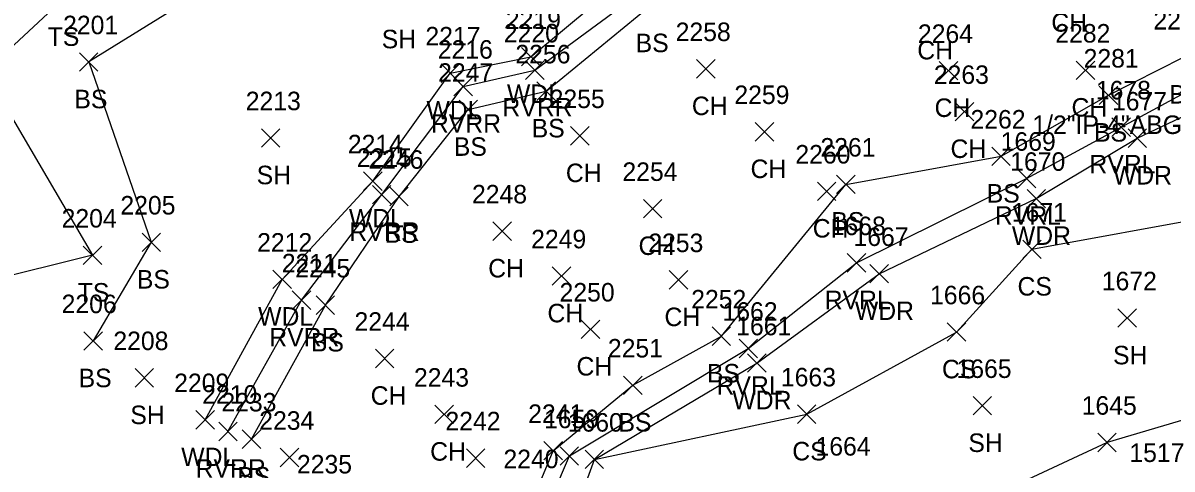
# Model space of a CAD drawing. Extents: x 1501299 to 1502485, y 381423 to 383765.
# Drawn here: x 1501473.5 to 1501597.6, y 383226.1 to 383274.3 of the extents above; entities that cross this region are included whole.
import ezdxf

# ---------------------------------------------------------------- set-up
doc = ezdxf.new("R2010")
doc.units = 0
for name, color, linetype in [('L_A', 7, 'Continuous'), ('L_I', 7, 'Continuous'), ('L_TIC', 7, 'Continuous'), ('LAWA', 7, 'Continuous'), ('LAWE', 7, 'Continuous'), ('LELB', 7, 'Continuous'), ('M_C', 7, 'Continuous')]:
    doc.layers.add(name, color=color, linetype=linetype)

msp = doc.modelspace()

# ---------------------------------------------------------------- linework, layer by layer
at = {"layer": 'L_TIC'}
for points in [[(1501479.6, 383269.06), (1501481.6, 383271.06)], [(1501481.6, 383269.06), (1501479.6, 383271.06)], [(1501527.36, 383269.63), (1501529.36, 383271.63)], [(1501529.36, 383269.63), (1501527.36, 383271.63)], [(1501518.66, 383267.85), (1501520.66, 383269.85)], [(1501520.66, 383267.85), (1501518.66, 383269.85)], [(1501527.78, 383268.18), (1501529.78, 383270.18)], [(1501529.78, 383268.18), (1501527.78, 383270.18)], [(1501546.26, 383268.32), (1501548.26, 383270.32)], [(1501548.26, 383268.32), (1501546.26, 383270.32)], [(1501572.48, 383268.12), (1501574.48, 383270.12)], [(1501574.48, 383268.12), (1501572.48, 383270.12)], [(1501587.27, 383268.16), (1501589.27, 383270.16)], [(1501589.27, 383268.16), (1501587.27, 383270.16)], [(1501520.04, 383266.42), (1501522.04, 383268.42)], [(1501522.04, 383266.42), (1501520.04, 383268.42)], [(1501529.01, 383265.91), (1501531.01, 383267.91)], [(1501531.01, 383265.91), (1501529.01, 383267.91)], [(1501589.76, 383265.46), (1501591.76, 383267.46)], [(1501591.76, 383265.46), (1501589.76, 383267.46)], [(1501520.6, 383263.92), (1501522.6, 383265.92)], [(1501522.6, 383263.92), (1501520.6, 383265.92)], [(1501574.2, 383263.69), (1501576.2, 383265.69)], [(1501576.2, 383263.69), (1501574.2, 383265.69)], [(1501552.6, 383261.52), (1501554.6, 383263.52)], [(1501554.6, 383261.52), (1501552.6, 383263.52)], [(1501591.13, 383262.02), (1501593.13, 383264.02)], [(1501593.13, 383262.02), (1501591.13, 383264.02)], [(1501499.25, 383260.85), (1501501.25, 383262.85)], [(1501501.25, 383260.85), (1501499.25, 383262.85)], [(1501532.65, 383261.08), (1501534.65, 383263.08)], [(1501534.65, 383261.08), (1501532.65, 383263.08)], [(1501592.87, 383260.82), (1501594.87, 383262.82)], [(1501594.87, 383260.82), (1501592.87, 383262.82)], [(1501578.15, 383258.87), (1501580.15, 383260.87)], [(1501580.15, 383258.87), (1501578.15, 383260.87)], [(1501580.91, 383256.47), (1501582.91, 383258.47)], [(1501582.91, 383256.47), (1501580.91, 383258.47)], [(1501510.28, 383256.19), (1501512.28, 383258.19)], [(1501512.28, 383256.19), (1501510.28, 383258.19)], [(1501559.32, 383255.09), (1501561.32, 383257.09)], [(1501561.32, 383255.09), (1501559.32, 383257.09)], [(1501561.38, 383255.84), (1501563.38, 383257.84)], [(1501563.38, 383255.84), (1501561.38, 383257.84)], [(1501511.25, 383254.73), (1501513.25, 383256.73)], [(1501513.25, 383254.73), (1501511.25, 383256.73)], [(1501513.12, 383254.52), (1501515.12, 383256.52)], [(1501515.12, 383254.52), (1501513.12, 383256.52)], [(1501581.96, 383254.3), (1501583.96, 383256.3)], [(1501583.96, 383254.3), (1501581.96, 383256.3)], [(1501540.51, 383253.21), (1501542.51, 383255.21)], [(1501542.51, 383253.21), (1501540.51, 383255.21)], [(1501524.26, 383250.78), (1501526.26, 383252.78)], [(1501526.26, 383250.78), (1501524.26, 383252.78)], [(1501486.36, 383249.58), (1501488.36, 383251.58)], [(1501488.36, 383249.58), (1501486.36, 383251.58)], [(1501480.01, 383248.17), (1501482.01, 383250.17)], [(1501482.01, 383248.17), (1501480.01, 383250.17)], [(1501581.49, 383248.82), (1501583.49, 383250.82)], [(1501583.49, 383248.82), (1501581.49, 383250.82)], [(1501562.53, 383247.35), (1501564.53, 383249.35)], [(1501564.53, 383247.35), (1501562.53, 383249.35)], [(1501500.49, 383245.57), (1501502.49, 383247.57)], [(1501502.49, 383245.57), (1501500.49, 383247.57)], [(1501530.66, 383245.93), (1501532.66, 383247.93)], [(1501532.66, 383245.93), (1501530.66, 383247.93)], [(1501543.3, 383245.52), (1501545.3, 383247.52)], [(1501545.3, 383245.52), (1501543.3, 383247.52)], [(1501564.99, 383246.18), (1501566.99, 383248.18)], [(1501566.99, 383246.18), (1501564.99, 383248.18)], [(1501502.59, 383243.33), (1501504.59, 383245.33)], [(1501504.59, 383243.33), (1501502.59, 383245.33)], [(1501505.16, 383242.78), (1501507.16, 383244.78)], [(1501507.16, 383242.78), (1501505.16, 383244.78)], [(1501591.77, 383241.39), (1501593.77, 383243.39)], [(1501593.77, 383241.39), (1501591.77, 383243.39)], [(1501533.8, 383240.18), (1501535.8, 383242.18)], [(1501535.8, 383240.18), (1501533.8, 383242.18)], [(1501547.94, 383239.43), (1501549.94, 383241.43)], [(1501549.94, 383239.43), (1501547.94, 383241.43)], [(1501573.33, 383239.88), (1501575.33, 383241.88)], [(1501575.33, 383239.88), (1501573.33, 383241.88)], [(1501480.07, 383238.92), (1501482.07, 383240.92)], [(1501482.07, 383238.92), (1501480.07, 383240.92)], [(1501550.85, 383238.1), (1501552.85, 383240.1)], [(1501552.85, 383238.1), (1501550.85, 383240.1)], [(1501511.57, 383237.02), (1501513.57, 383239.02)], [(1501513.57, 383237.02), (1501511.57, 383239.02)], [(1501551.76, 383236.53), (1501553.76, 383238.53)], [(1501553.76, 383236.53), (1501551.76, 383238.53)], [(1501485.6, 383234.93), (1501487.6, 383236.93)], [(1501487.6, 383234.93), (1501485.6, 383236.93)], [(1501538.38, 383234.13), (1501540.38, 383236.13)], [(1501540.38, 383234.13), (1501538.38, 383236.13)], [(1501576.13, 383231.92), (1501578.13, 383233.92)], [(1501578.13, 383231.92), (1501576.13, 383233.92)], [(1501492.17, 383230.39), (1501494.17, 383232.39)], [(1501494.17, 383230.39), (1501492.17, 383232.39)], [(1501517.99, 383230.98), (1501519.99, 383232.98)], [(1501519.99, 383230.98), (1501517.99, 383232.98)], [(1501557.16, 383231.01), (1501559.16, 383233.01)], [(1501559.16, 383231.01), (1501557.16, 383233.01)], [(1501494.64, 383229.14), (1501496.64, 383231.14)], [(1501496.64, 383229.14), (1501494.64, 383231.14)], [(1501497.19, 383228.3), (1501499.19, 383230.3)], [(1501499.19, 383228.3), (1501497.19, 383230.3)], [(1501589.6, 383227.95), (1501591.6, 383229.95)], [(1501591.6, 383227.95), (1501589.6, 383229.95)], [(1501529.77, 383227.06), (1501531.77, 383229.06)], [(1501531.77, 383227.06), (1501529.77, 383229.06)], [(1501501.28, 383226.32), (1501503.28, 383228.32)], [(1501503.28, 383226.32), (1501501.28, 383228.32)], [(1501521.39, 383226.26), (1501523.39, 383228.26)], [(1501523.39, 383226.26), (1501521.39, 383228.26)], [(1501531.52, 383226.49), (1501533.52, 383228.49)], [(1501533.52, 383226.49), (1501531.52, 383228.49)], [(1501534.22, 383226.12), (1501536.22, 383228.12)], [(1501536.22, 383226.12), (1501534.22, 383228.12)], [(1501534.22, 383226.12), (1501536.22, 383228.12)], [(1501536.22, 383226.12), (1501534.22, 383228.12)]]:
    msp.add_lwpolyline(points, dxfattribs=at)
at = {"layer": 'LAWA'}
for points in [[(1501493.17, 383231.39), (1501501.49, 383246.57), (1501511.28, 383257.19), (1501519.66, 383268.85), (1501528.36, 383270.63), (1501542.05, 383282.05), (1501551.39, 383287.43), (1501560.18, 383293.04)], [(1501523.12, 383213.31), (1501532.43, 383219.38), (1501535.22, 383227.12), (1501552.76, 383237.53), (1501565.99, 383247.18), (1501582.96, 383255.3), (1501593.87, 383261.82), (1501604.57, 383266.91)]]:
    msp.add_lwpolyline(points, dxfattribs=at)
at = {"layer": 'LAWE'}
for points in [[(1501495.64, 383230.14), (1501503.59, 383244.33), (1501512.25, 383255.73), (1501521.04, 383267.42), (1501528.78, 383269.18), (1501542.64, 383279.39), (1501552.31, 383285.91), (1501562.62, 383292.35), (1501575.76, 383300.88), (1501583.22, 383301.34), (1501587.9, 383304.38)], [(1501505.16, 383203.17), (1501520.7, 383214.78), (1501528.92, 383219.09), (1501532.52, 383227.49), (1501551.85, 383239.1), (1501563.53, 383248.35), (1501581.91, 383257.47), (1501592.13, 383263.02), (1501602.49, 383268.62), (1501606.54, 383268.13), (1501609.9, 383267.24)]]:
    msp.add_lwpolyline(points, dxfattribs=at)
at = {"layer": 'LELB'}
for points in [[(1501498.19, 383229.3), (1501506.16, 383243.78), (1501514.12, 383255.52), (1501521.6, 383264.92), (1501530.01, 383266.91), (1501541.24, 383276.12), (1501565.52, 383288.26), (1501578.59, 383296.73), (1501585.35, 383299.26), (1501590.26, 383300.86), (1501600.8, 383297.99), (1501605.17, 383301.4), (1501610.7, 383306.05), (1501616.47, 383310.93), (1501623.41, 383316.64), (1501624.75, 383320.37)], [(1501529.79, 383319.02), (1501508.47, 383318.79), (1501498.45, 383314.16), (1501488.16, 383291.02), (1501493.84, 383282.99), (1501477.76, 383276.8), (1501469.37, 383268.99), (1501481.01, 383249.17), (1501469.56, 383246.34)], [(1501529.79, 383319.02), (1501511.35, 383311.94), (1501505.3, 383294.67), (1501497.78, 383280.73), (1501480.6, 383270.06), (1501487.36, 383250.58), (1501481.07, 383239.92)], [(1501528.75, 383223.17), (1501530.77, 383228.06), (1501539.38, 383235.13), (1501548.94, 383240.43), (1501562.38, 383256.84), (1501579.15, 383259.87), (1501590.76, 383266.46), (1501598.87, 383270.57)], [(1501535.22, 383227.12), (1501558.16, 383232.01), (1501574.33, 383240.88), (1501582.49, 383249.82), (1501602.25, 383253.43), (1501611.93, 383256.47)], [(1501605.35, 383233.31), (1501590.6, 383228.95), (1501573.55, 383221), (1501565.09, 383213.34), (1501549.82, 383204.98), (1501532.49, 383198.66), (1501516.24, 383190.97)]]:
    msp.add_lwpolyline(points, dxfattribs=at)

# ---------------------------------------------------------------- texts
at = {"layer": 'L_A'}
for s, p in [('CH', (1501584.58, 383273.34)), ('TS', (1501476.17, 383271.8)), ('SH', (1501512.25, 383271.54)), ('BS', (1501539.68, 383271.12)), ('CH', (1501570.1, 383270.34)), ('BS', (1501479.05, 383265.06)), ('WDL', (1501525.78, 383265.63)), ('BS', (1501597.31, 383265.57)), ('WDL', (1501517.08, 383263.85)), ('RVRR', (1501525.29, 383264.18)), ('CH', (1501545.75, 383264.32)), ('CH', (1501571.97, 383264.12)), ('CH', (1501586.76, 383264.16)), ('RVRR', (1501517.56, 383262.42)), ('BS', (1501528.45, 383261.91)), ('BS', (1501589.2, 383261.46)), ('BS', (1501520.04, 383259.92)), ('CH', (1501573.69, 383259.69)), ('RVRL', (1501588.7, 383258.02)), ('SH', (1501498.74, 383256.85)), ('CH', (1501532.14, 383257.08)), ('CH', (1501552.09, 383257.52)), ('WDR', (1501591.23, 383256.82)), ('BS', (1501577.6, 383254.87)), ('WDL', (1501508.7, 383252.19)), ('BS', (1501560.82, 383251.84)), ('RVRL', (1501578.48, 383252.47)), ('RVRR', (1501508.76, 383250.73)), ('BS', (1501512.56, 383250.52)), ('CH', (1501558.81, 383251.09)), ('WDR', (1501580.32, 383250.3)), ('CH', (1501539.99, 383249.21)), ('CH', (1501523.75, 383246.78)), ('BS', (1501485.8, 383245.58)), ('TS', (1501479.41, 383244.17)), ('CS', (1501580.93, 383244.82)), ('RVRL', (1501560.1, 383243.35)), ('WDL', (1501498.9, 383241.57)), ('CH', (1501530.15, 383241.93)), ('CH', (1501542.79, 383241.52)), ('WDR', (1501563.36, 383242.18)), ('RVRR', (1501500.1, 383239.33)), ('BS', (1501504.6, 383238.78)), ('SH', (1501591.25, 383237.39)), ('CH', (1501533.29, 383236.18)), ('BS', (1501547.38, 383235.43)), ('CS', (1501572.77, 383235.88)), ('BS', (1501479.51, 383234.92)), ('RVRL', (1501548.42, 383234.1)), ('CH', (1501511.06, 383233.02)), ('WDR', (1501550.13, 383232.53)), ('SH', (1501485.09, 383230.93)), ('BS', (1501537.82, 383230.13)), ('SH', (1501575.62, 383227.92)), ('CH', (1501517.48, 383226.98)), ('CS', (1501556.6, 383227.01)), ('WDL', (1501490.59, 383226.39)), ('RVRR', (1501492.15, 383225.14)), ('BS', (1501496.64, 383224.3))]:
    msp.add_text(s, height=2, dxfattribs=at).set_placement(p)
at = {"layer": 'L_I'}
for s, p in [('2201', (1501477.83, 383273.06)), ('2219', (1501525.66, 383273.63)), ('2283', (1501595.61, 383273.57)), ('2217', (1501516.97, 383271.85)), ('2220', (1501525.44, 383272.18)), ('2258', (1501544, 383272.32)), ('2264', (1501570.17, 383272.12)), ('2282', (1501585.01, 383272.16)), ('2216', (1501518.3, 383270.42)), ('2256', (1501526.69, 383269.91)), ('2281', (1501588.07, 383269.46)), ('2247', (1501518.34, 383267.92)), ('2263', (1501571.89, 383267.69)), ('2255', (1501530.39, 383265.08)), ('2259', (1501550.34, 383265.52)), ('1678', (1501589.39, 383266.02)), ('2213', (1501497.56, 383264.85)), ('1677', (1501591.13, 383264.82)), ('2262', (1501575.85, 383262.87)), ('2214', (1501508.59, 383260.19)), ('1669', (1501579.11, 383260.47)), ('2260', (1501556.93, 383259.09)), ('2261', (1501559.64, 383259.84)), ('2215', (1501509.56, 383258.73)), ('2246', (1501510.8, 383258.52)), ('1670', (1501580.14, 383258.3)), ('2254', (1501538.25, 383257.21)), ('2248', (1501522, 383254.78)), ('2205', (1501484.02, 383253.58)), ('1671', (1501580.31, 383252.82)), ('2204', (1501477.67, 383252.17)), ('1668', (1501560.75, 383251.35)), ('1667', (1501563.21, 383250.18)), ('2212', (1501498.79, 383249.57)), ('2249', (1501528.39, 383249.93)), ('2253', (1501541.04, 383249.52)), ('2211', (1501501.46, 383247.33)), ('2245', (1501502.9, 383246.78)), ('1672', (1501590.03, 383245.39)), ('2250', (1501531.46, 383244.18)), ('1666', (1501571.48, 383243.88)), ('2206', (1501477.67, 383242.92)), ('2252', (1501545.68, 383243.43)), ('1662', (1501549.06, 383242.1)), ('2244', (1501509.31, 383241.02)), ('1661', (1501550.54, 383240.53)), ('2208', (1501483.26, 383238.93)), ('2251', (1501536.68, 383238.13)), ('1665', (1501574.34, 383235.92)), ('2209', (1501489.83, 383234.39)), ('2243', (1501515.73, 383234.98)), ('1663', (1501555.37, 383235.01)), ('2210', (1501492.86, 383233.14)), ('2233', (1501494.93, 383232.3)), ('1645', (1501587.86, 383231.95)), ('2234', (1501499.02, 383230.32)), ('2242', (1501519.13, 383230.26)), ('2241', (1501528.07, 383231.06)), ('1659', (1501529.78, 383230.49)), ('1660', (1501532.34, 383230.12)), ('1660', (1501532.34, 383230.12)), ('1664', (1501559.11, 383227.53)), ('1517', (1501593.01, 383226.84)), ('2235', (1501503.09, 383225.6)), ('2240', (1501525.4, 383226.17))]:
    msp.add_text(s, height=2, dxfattribs=at).set_placement(p)
at = {"layer": 'M_C'}
msp.add_text('1/2"IP-4"ABG AT EDGE BROOK DJK ', height=2, dxfattribs=at).set_placement((1501582.53, 383262.28))

doc.saveas('drawing.dxf')
